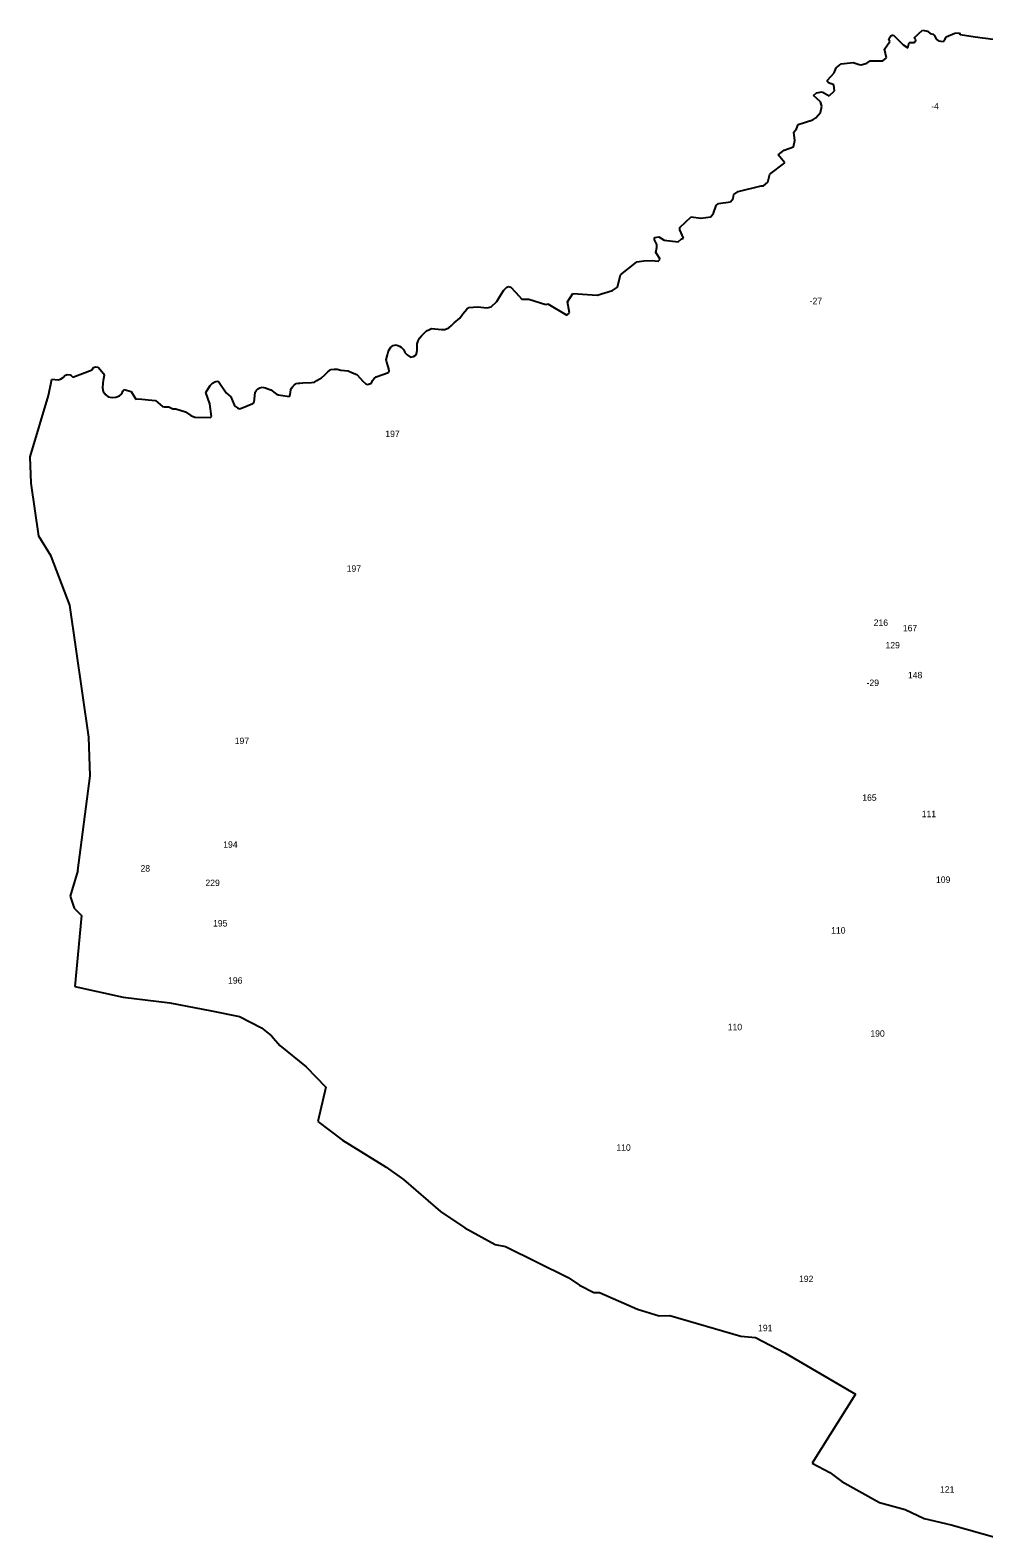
# Model space of a CAD drawing. Extents: x -788870 to -783053, y -967261 to -964403.
# Drawn here: x -788870 to -787389, y -966821 to -964481 of the extents above; entities that cross this region are included whole.
import ezdxf

# ---------------------------------------------------------------- set-up
doc = ezdxf.new("R2010")
doc.units = 0
doc.layers.add('Vrstva 13', color=7, linetype='Continuous')
doc.layers.add('Vrstva 15', color=7, linetype='Continuous')

msp = doc.modelspace()

# ---------------------------------------------------------------- linework, layer by layer
at = {"layer": 'Vrstva 13'}
for p, q in [((-787497.48, -964493.02), (-787484.15, -964480.85)), ((-787484.15, -964480.85), (-787476.62, -964482.59)), ((-787476.62, -964482.59), (-787472.57, -964486.21)), ((-787543.09, -964510.56), (-787535.28, -964498.53)), ((-787536.44, -964494.32), (-787533.4, -964489.54)), ((-787535.28, -964498.53), (-787536.44, -964494.32)), ((-787533.4, -964489.54), (-787531.22, -964488.38)), ((-787531.22, -964488.38), (-787529.49, -964488.67)), ((-787529.49, -964488.67), (-787514.57, -964503.6)), ((-787514.57, -964503.6), (-787506.89, -964508.09)), ((-787506.89, -964508.09), (-787505.15, -964500.26)), ((-787505.15, -964500.26), (-787497.91, -964499.83)), ((-787497.91, -964499.83), (-787495.16, -964498.38)), ((-787494.58, -964495.63), (-787497.48, -964493.02)), ((-787495.16, -964498.38), (-787494.58, -964495.63)), ((-787472.57, -964486.21), (-787468.22, -964486.94)), ((-787468.22, -964486.94), (-787465.91, -964488.96)), ((-787465.91, -964488.96), (-787463.3, -964494.9)), ((-787463.3, -964494.9), (-787459.24, -964497.22)), ((-787459.24, -964497.22), (-787452.43, -964498.23)), ((-787452.43, -964498.23), (-787448.96, -964494.9)), ((-787448.96, -964494.9), (-787447.37, -964490.99)), ((-787447.37, -964490.99), (-787434.33, -964485.34)), ((-787434.33, -964485.34), (-787427.52, -964485.05)), ((-787427.52, -964485.05), (-787425.64, -964487.51)), ((-787425.64, -964487.51), (-787402.61, -964490.99)), ((-787402.61, -964490.99), (-787374.37, -964494.75)), ((-787570.9, -964532.15), (-787565.69, -964528.67)), ((-787565.69, -964528.67), (-787545.7, -964528.38)), ((-787545.7, -964528.38), (-787540.05, -964523.89)), ((-787540.05, -964523.89), (-787543.09, -964510.56)), ((-787631.87, -964558.23), (-787621.45, -964547.07)), ((-787621.45, -964547.07), (-787618.26, -964539.25)), ((-787618.26, -964539.25), (-787610.58, -964533.16)), ((-787610.58, -964533.16), (-787592.05, -964531.13)), ((-787592.05, -964531.13), (-787582.63, -964534.18)), ((-787582.63, -964534.18), (-787579.74, -964534.75)), ((-787579.74, -964534.75), (-787570.9, -964532.15)), ((-787648.96, -964578.22), (-787640.13, -964576.63)), ((-787640.13, -964576.63), (-787629.41, -964582.71)), ((-787631.87, -964560.69), (-787631.87, -964558.23)), ((-787630.28, -964562.72), (-787631.87, -964560.69)), ((-787622.02, -964565.91), (-787630.28, -964562.72)), ((-787629.41, -964582.71), (-787620.87, -964575.03)), ((-787620.87, -964575.03), (-787622.02, -964565.91)), ((-787653.31, -964582.13), (-787648.96, -964578.22)), ((-787642.59, -964592.28), (-787653.31, -964582.13)), ((-787642.73, -964608.79), (-787640.85, -964598.65)), ((-787640.85, -964598.65), (-787642.59, -964592.28)), ((-787677.21, -964627.19), (-787654.47, -964619.94)), ((-787654.47, -964619.94), (-787649.69, -964616.76)), ((-787649.69, -964616.76), (-787642.73, -964608.79)), ((-787684.16, -964639.36), (-787679.81, -964633.85)), ((-787682.42, -964652.4), (-787684.16, -964639.36)), ((-787679.81, -964633.85), (-787677.21, -964627.19)), ((-787708.35, -964674.57), (-787699.37, -964667.32)), ((-787699.37, -964667.32), (-787684.45, -964661.96)), ((-787684.45, -964661.96), (-787682.42, -964652.4)), ((-787721.53, -964704.41), (-787698.06, -964687.03)), ((-787698.06, -964687.03), (-787708.35, -964674.57)), ((-787731.08, -964722.38), (-787724.57, -964716.58)), ((-787724.57, -964716.58), (-787721.53, -964704.41)), ((-787778.15, -964742.23), (-787777.14, -964736)), ((-787777.14, -964736), (-787770.77, -964731.51)), ((-787770.77, -964731.51), (-787735, -964722.67)), ((-787735, -964722.67), (-787731.08, -964722.38)), ((-787812.77, -964770.77), (-787808.86, -964764.98)), ((-787808.86, -964764.98), (-787804.66, -964753.24)), ((-787804.66, -964753.24), (-787801.18, -964750.2)), ((-787801.18, -964750.2), (-787782.21, -964747.59)), ((-787782.21, -964747.59), (-787778.15, -964742.23)), ((-787861.14, -964790.77), (-787861, -964787)), ((-787861, -964787), (-787843.33, -964770.63)), ((-787843.33, -964770.63), (-787828.27, -964772.51)), ((-787828.27, -964772.51), (-787812.77, -964770.77)), ((-787900.68, -964806.42), (-787900.39, -964802.66)), ((-787896.92, -964813.81), (-787900.68, -964806.42)), ((-787900.39, -964802.66), (-787893.88, -964801.79)), ((-787893.88, -964801.79), (-787885.19, -964807)), ((-787885.19, -964807), (-787863.9, -964809.47)), ((-787863.9, -964809.47), (-787858.68, -964804.54)), ((-787855.35, -964803.53), (-787861.14, -964790.77)), ((-787858.68, -964804.54), (-787855.35, -964803.53)), ((-787898.51, -964825.84), (-787896.92, -964818.3)), ((-787891.71, -964836.56), (-787898.51, -964825.84)), ((-787896.92, -964818.3), (-787896.92, -964813.81)), ((-787953.11, -964860.75), (-787931.1, -964842.93)), ((-787931.1, -964842.93), (-787927.62, -964840.33)), ((-787927.62, -964840.33), (-787917.05, -964839.17)), ((-787917.05, -964839.17), (-787904.31, -964838.44)), ((-787904.31, -964838.44), (-787894.89, -964839.6)), ((-787894.89, -964839.6), (-787891.71, -964836.56)), ((-788134.29, -964884.23), (-788129.65, -964879.88)), ((-788129.65, -964879.88), (-788127.04, -964878.72)), ((-788127.04, -964878.72), (-788123.71, -964879.88)), ((-788123.71, -964879.88), (-788116.91, -964886.98)), ((-787965.57, -964884.8), (-787958.03, -964880.02)), ((-787958.03, -964880.02), (-787953.11, -964860.75)), ((-788153.98, -964910.6), (-788145.44, -964901.9)), ((-788145.44, -964901.9), (-788139.07, -964891.91)), ((-788139.07, -964891.91), (-788134.29, -964884.23)), ((-788116.91, -964886.98), (-788110.82, -964893.64)), ((-788110.82, -964893.64), (-788106.48, -964898.43)), ((-788106.48, -964898.43), (-788095.33, -964898.28)), ((-788095.33, -964898.28), (-788069.27, -964906.97)), ((-788035.52, -964902.62), (-788027.26, -964889.87)), ((-788032.33, -964919.87), (-788035.52, -964902.62)), ((-788027.26, -964889.87), (-787989.46, -964892.33)), ((-787989.46, -964892.33), (-787965.57, -964884.8)), ((-788211.34, -964935.23), (-788202.65, -964927.69)), ((-788202.65, -964927.69), (-788198.01, -964921.03)), ((-788198.01, -964921.03), (-788191.93, -964914.07)), ((-788191.93, -964914.07), (-788188.74, -964911.32)), ((-788188.74, -964911.32), (-788175.27, -964910.31)), ((-788175.27, -964910.31), (-788160.21, -964912.04)), ((-788160.21, -964912.04), (-788153.98, -964910.6)), ((-788069.27, -964906.97), (-788066.08, -964905.81)), ((-788066.08, -964905.81), (-788036.39, -964923.34)), ((-788036.39, -964923.34), (-788032.33, -964919.87)), ((-788262.03, -964955.22), (-788258.69, -964951.89)), ((-788258.69, -964951.89), (-788254.21, -964947.83)), ((-788254.21, -964947.83), (-788251.02, -964945.8)), ((-788251.02, -964945.8), (-788246.82, -964943.77)), ((-788246.82, -964943.77), (-788241.32, -964944.35)), ((-788241.32, -964944.35), (-788231.03, -964945.51)), ((-788231.03, -964945.51), (-788226.11, -964945.51)), ((-788226.11, -964945.51), (-788219.74, -964943.05)), ((-788219.74, -964943.05), (-788215.39, -964939.43)), ((-788215.39, -964939.43), (-788211.34, -964935.23)), ((-788313.58, -964978.54), (-788309.96, -964973.04)), ((-788309.96, -964973.04), (-788306.34, -964970.29)), ((-788306.34, -964970.29), (-788301.41, -964969.27)), ((-788301.41, -964969.27), (-788296.5, -964971.16)), ((-788296.5, -964971.16), (-788293.89, -964973.18)), ((-788293.89, -964973.18), (-788289.83, -964977.1)), ((-788268.69, -964967.97), (-788267.53, -964963.04)), ((-788268.69, -964973.76), (-788268.69, -964967.97)), ((-788268.69, -964977.53), (-788268.69, -964973.76)), ((-788267.53, -964963.04), (-788265.5, -964958.84)), ((-788265.5, -964958.84), (-788262.03, -964955.22)), ((-788317.2, -964992.45), (-788315.17, -964984.63)), ((-788316.47, -964994.92), (-788317.2, -964992.45)), ((-788314.16, -965002.74), (-788316.47, -964994.92)), ((-788315.17, -964984.63), (-788313.58, -964978.54)), ((-788289.83, -964977.1), (-788288.24, -964981.3)), ((-788288.24, -964981.3), (-788284.33, -964985.06)), ((-788284.33, -964985.06), (-788279.41, -964988.69)), ((-788279.41, -964988.69), (-788274.63, -964987.53)), ((-788274.63, -964987.53), (-788270.43, -964984.77)), ((-788270.43, -964984.77), (-788269.27, -964981.3)), ((-788269.27, -964981.3), (-788268.69, -964977.53)), ((-788822.49, -965022.83), (-788818.58, -965020.01)), ((-788818.58, -965020.01), (-788815.97, -965016.96)), ((-788815.97, -965016.96), (-788812.2, -965015.15)), ((-788812.2, -965015.15), (-788807.56, -965015.88)), ((-788807.56, -965015.88), (-788805.97, -965017.04)), ((-788805.97, -965017.04), (-788803.8, -965019.35)), ((-788803.8, -965019.35), (-788773.53, -965007.91)), ((-788773.53, -965007.91), (-788771.37, -965004.65)), ((-788771.37, -965004.65), (-788768.18, -965003.42)), ((-788768.18, -965003.42), (-788764.42, -965004.14)), ((-788764.42, -965004.14), (-788756.02, -965013.92)), ((-788755.28, -965019.35), (-788756.44, -965024.57)), ((-788756.02, -965013.92), (-788755, -965016.74)), ((-788755, -965016.74), (-788755.28, -965019.35)), ((-788424.51, -965024.92), (-788417.7, -965020.57)), ((-788417.7, -965020.57), (-788412.06, -965015.78)), ((-788412.06, -965015.78), (-788407.86, -965011)), ((-788407.86, -965011), (-788403.23, -965007.81)), ((-788403.23, -965007.81), (-788398.01, -965007.23)), ((-788398.01, -965007.23), (-788392.94, -965007.23)), ((-788392.94, -965007.23), (-788387.59, -965008.83)), ((-788387.59, -965008.83), (-788375.85, -965009.84)), ((-788375.85, -965009.84), (-788369.19, -965012.74)), ((-788369.19, -965012.74), (-788362.82, -965015.63)), ((-788362.82, -965015.63), (-788357.61, -965020.85)), ((-788357.61, -965020.85), (-788353.12, -965025.78)), ((-788338.2, -965024.47), (-788335.59, -965021.57)), ((-788335.59, -965021.57), (-788332.7, -965019.11)), ((-788332.7, -965019.11), (-788313.43, -965012.16)), ((-788312.71, -965006.36), (-788314.16, -965002.74)), ((-788313.43, -965012.16), (-788312.42, -965009.98)), ((-788312.42, -965009.98), (-788312.71, -965006.36)), ((-788841.45, -965047.75), (-788836.82, -965025.15)), ((-788836.82, -965025.15), (-788836.24, -965022.69)), ((-788836.24, -965022.69), (-788826.32, -965023.48)), ((-788826.32, -965023.48), (-788822.49, -965022.83)), ((-788757.16, -965029.06), (-788757.45, -965036.16)), ((-788757.45, -965036.16), (-788756.24, -965041.74)), ((-788756.44, -965024.57), (-788757.16, -965029.06)), ((-788756.24, -965041.74), (-788752.48, -965046.81)), ((-788731.19, -965048.69), (-788727.62, -965045.43)), ((-788727.62, -965045.43), (-788725.83, -965041.45)), ((-788725.83, -965041.45), (-788725.01, -965039.49)), ((-788725.01, -965039.49), (-788724.02, -965038.92)), ((-788724.02, -965038.92), (-788712.94, -965041.74)), ((-788712.94, -965041.74), (-788705.56, -965053.9)), ((-788596.86, -965043.33), (-788590.34, -965032.32)), ((-788591.07, -965061.01), (-788596.86, -965043.33)), ((-788590.34, -965032.32), (-788586.87, -965028.7)), ((-788586.87, -965028.7), (-788583.1, -965026.67)), ((-788583.1, -965026.67), (-788579.77, -965025.65)), ((-788579.77, -965025.65), (-788577.6, -965026.38)), ((-788577.6, -965026.38), (-788565.58, -965044.05)), ((-788565.58, -965044.05), (-788558.05, -965049.85)), ((-788522.13, -965058.69), (-788520.25, -965042.75)), ((-788520.25, -965042.75), (-788518.51, -965039.56)), ((-788518.51, -965039.56), (-788516.48, -965037.53)), ((-788516.48, -965037.53), (-788513.44, -965035.94)), ((-788513.44, -965035.94), (-788509.53, -965035.07)), ((-788509.53, -965035.07), (-788504.6, -965036.23)), ((-788504.6, -965036.23), (-788500.55, -965037.53)), ((-788500.55, -965037.53), (-788496.35, -965039.13)), ((-788496.35, -965039.13), (-788487.51, -965046.07)), ((-788465.93, -965046.22), (-788465.06, -965039.41)), ((-788465.06, -965039.41), (-788463.9, -965036.65)), ((-788463.9, -965036.65), (-788461.88, -965033.9)), ((-788461.88, -965033.9), (-788459.7, -965031.87)), ((-788459.7, -965031.87), (-788456.95, -965029.55)), ((-788456.95, -965029.55), (-788453.77, -965028.68)), ((-788453.77, -965028.68), (-788450.87, -965028.68)), ((-788450.87, -965028.68), (-788446.38, -965028.39)), ((-788446.38, -965028.39), (-788432.77, -965027.96)), ((-788432.77, -965027.96), (-788428.57, -965027.09)), ((-788428.57, -965027.09), (-788424.51, -965024.92)), ((-788353.12, -965025.78), (-788348.63, -965030.12)), ((-788348.63, -965030.12), (-788345.87, -965030.7)), ((-788345.87, -965030.7), (-788340.08, -965028.82)), ((-788340.08, -965028.82), (-788338.2, -965024.47)), ((-788869.84, -965143.37), (-788841.45, -965047.75)), ((-788752.48, -965046.81), (-788748.57, -965050.07)), ((-788748.57, -965050.07), (-788742.34, -965051.01)), ((-788742.34, -965051.01), (-788736.69, -965050.72)), ((-788736.69, -965050.72), (-788731.19, -965048.69)), ((-788705.56, -965053.9), (-788701, -965053.11)), ((-788701, -965053.11), (-788686.66, -965054.77)), ((-788686.66, -965054.77), (-788675.07, -965055.5)), ((-788675.07, -965055.5), (-788664.21, -965065.06)), ((-788664.21, -965065.06), (-788661.82, -965065.64)), ((-788661.82, -965065.64), (-788654.58, -965065.42)), ((-788654.58, -965065.42), (-788648.28, -965068.82)), ((-788648.28, -965068.82), (-788643.43, -965068.9)), ((-788643.43, -965068.9), (-788628.57, -965073.32)), ((-788588.31, -965080.42), (-788591.07, -965061.01)), ((-788558.05, -965049.85), (-788553.12, -965062.6)), ((-788553.12, -965062.6), (-788551.09, -965064.92)), ((-788551.09, -965064.92), (-788547.76, -965067.24)), ((-788547.76, -965067.24), (-788544.87, -965068.68)), ((-788544.87, -965068.68), (-788541.82, -965067.81)), ((-788541.82, -965067.81), (-788524.01, -965060.57)), ((-788524.01, -965060.57), (-788522.13, -965058.69)), ((-788487.51, -965046.07), (-788484.04, -965047.08)), ((-788484.04, -965047.08), (-788467.82, -965049.55)), ((-788467.82, -965049.55), (-788466.51, -965048.24)), ((-788466.51, -965048.24), (-788465.93, -965046.22)), ((-788628.57, -965073.32), (-788620.46, -965079.12)), ((-788620.46, -965079.12), (-788614.09, -965081.58)), ((-788614.09, -965081.58), (-788589.76, -965082.16)), ((-788589.76, -965082.16), (-788588.31, -965080.42)), ((-788868.1, -965183.94), (-788869.84, -965143.37)), ((-788856.52, -965266.23), (-788868.1, -965183.94)), ((-788837.4, -965297.52), (-788856.52, -965266.23)), ((-788808.44, -965373.44), (-788837.4, -965297.52)), ((-788778.89, -965578.59), (-788808.44, -965373.44)), ((-788776.58, -965638.27), (-788778.89, -965578.59)), ((-788795.69, -965785.47), (-788776.58, -965638.27)), ((-788795.69, -965785.47), (-788807.85, -965825.22)), ((-788807.85, -965825.22), (-788801.53, -965843.6)), ((-788801.53, -965843.6), (-788790.05, -965855.08)), ((-788790.05, -965855.08), (-788800.38, -965965.33)), ((-788800.38, -965965.33), (-788725.63, -965981.84)), ((-788725.63, -965981.84), (-788652.73, -965990.74)), ((-788652.73, -965990.74), (-788588.16, -966003.08)), ((-788588.16, -966003.08), (-788544.67, -966012.12)), ((-788544.67, -966012.12), (-788510.67, -966029.78)), ((-788510.67, -966029.78), (-788494.89, -966041.84)), ((-788494.89, -966041.84), (-788481.97, -966057.06)), ((-788481.97, -966057.06), (-788441.51, -966090.07)), ((-788441.51, -966090.07), (-788410.8, -966121.65)), ((-788410.8, -966121.65), (-788423.28, -966174.91)), ((-788423.28, -966174.91), (-788384.97, -966203.76)), ((-788384.97, -966203.76), (-788316.96, -966245.68)), ((-788316.96, -966245.68), (-788290.27, -966264.91)), ((-788290.27, -966264.91), (-788232.87, -966314.87)), ((-788232.87, -966314.87), (-788194.99, -966339.85)), ((-788194.99, -966339.85), (-788147.64, -966365.98)), ((-788147.64, -966365.98), (-788131.85, -966369.14)), ((-788131.85, -966369.14), (-788034.56, -966417.08)), ((-788034.56, -966417.08), (-788016.78, -966428.86)), ((-788016.78, -966428.86), (-787994.68, -966440.34)), ((-787994.68, -966440.34), (-787985.78, -966440.34)), ((-787985.78, -966440.34), (-787926.66, -966466.18)), ((-787926.66, -966466.18), (-787893.08, -966476.8)), ((-787893.08, -966476.8), (-787876.73, -966476.23)), ((-787876.73, -966476.23), (-787766.37, -966508.24)), ((-787766.37, -966508.24), (-787743.55, -966510.1)), ((-787743.55, -966510.1), (-787697.92, -966534.22)), ((-787697.92, -966534.22), (-787588.29, -966598.53)), ((-787588.29, -966598.53), (-787655.74, -966705.33)), ((-787655.74, -966705.33), (-787628.18, -966719.98)), ((-787628.18, -966719.98), (-787609.82, -966733.76)), ((-787609.82, -966733.76), (-787550.98, -966766.2)), ((-787550.98, -966766.2), (-787511.09, -966777.39)), ((-787511.09, -966777.39), (-787481.82, -966791.18)), ((-787481.82, -966791.18), (-787439.92, -966800.94)), ((-787439.92, -966800.94), (-787368.18, -966821.32))]:
    msp.add_line(p, q, dxfattribs=at)

# ---------------------------------------------------------------- texts
at = {"layer": 'Vrstva 15'}
for s, p in [('-4', (-787470.886, -964604.01)), ('-27', (-787659.529, -964906.28)), ('197', (-788318.383, -965112.48)), ('197', (-788378.383, -965321.67)), ('216', (-787560.134, -965405.71)), ('167', (-787514.823, -965414.04)), ('129', (-787541.764, -965440.56)), ('-29', (-787571.144, -965498.96)), ('148', (-787506.896, -965487.02)), ('197', (-788552.193, -965589.11)), ('165', (-787577.874, -965677.2)), ('111', (-787485.5, -965702.59)), ('194', (-788570.04, -965750.07)), ('28', (-788698.496, -965787.02)), ('109', (-787463.404, -965804.57)), ('229', (-788597.69, -965809.51)), ('195', (-788585.894, -965872.32)), ('110', (-787626.146, -965883.31)), ('196', (-788562.508, -965961.03)), ('110', (-787786.716, -966033.35)), ('190', (-787565.284, -966043.45)), ('110', (-787959.636, -966220.47)), ('192', (-787676.044, -966424.3)), ('191', (-787739.608, -966500.54)), ('121', (-787457.116, -966751.14))]:
    msp.add_text(s, height=10, dxfattribs=at).set_placement(p)

doc.saveas('drawing.dxf')
